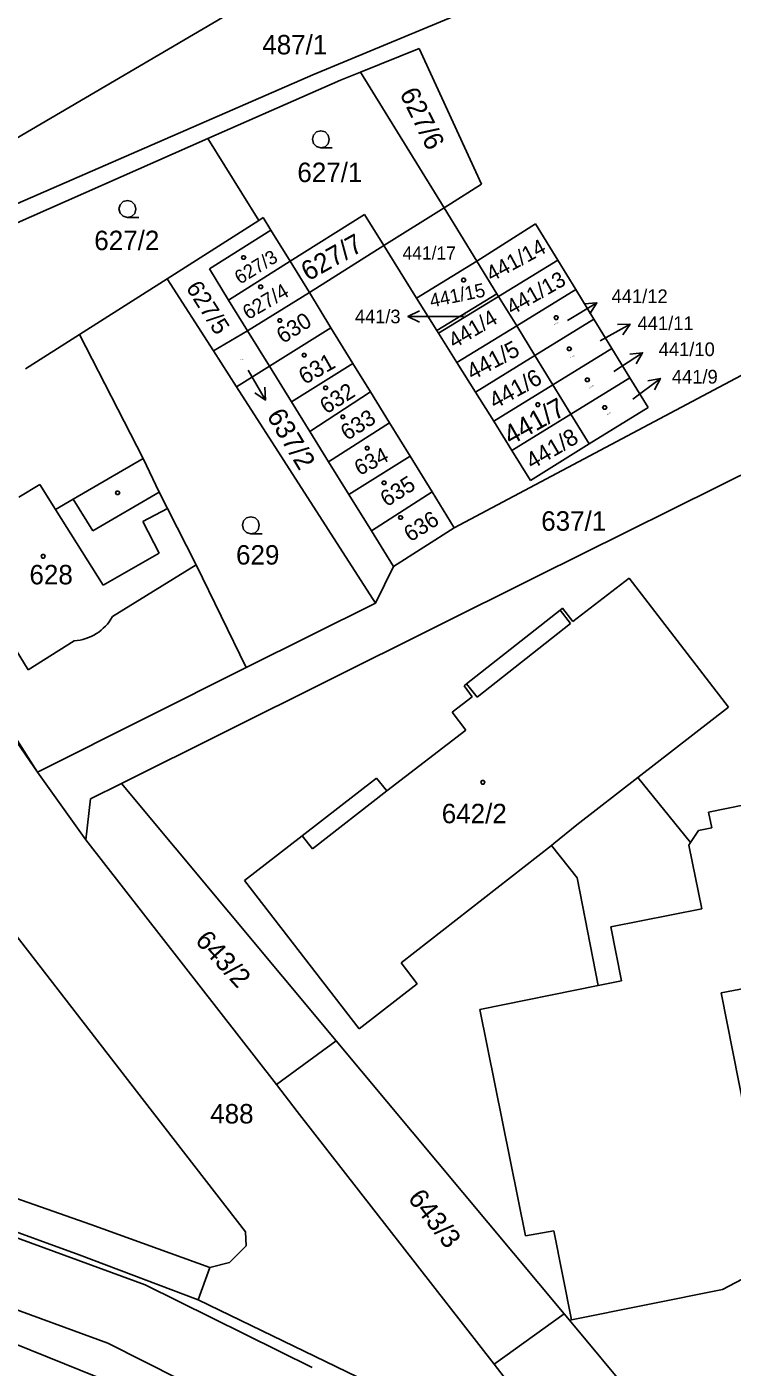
# Model space of a CAD drawing. Extents: x -621797 to -620972, y -1175539 to -1174697.
# Drawn here: x -621375.1 to -621313.4, y -1174986.3 to -1174869.1 of the extents above; entities that cross this region are included whole.
import ezdxf

# ---------------------------------------------------------------- set-up
doc = ezdxf.new("R2010")
doc.units = 0
for name, color, linetype in [('INZ mimo EON - nadz', 7, 'Continuous'), ('Rozvod plynu EON', 7, 'Continuous'), ('SDEL EON', 7, 'Continuous'), ('SDEL EON - popis', 7, 'Continuous'), ('Silnoproud EON', 7, 'Continuous'), ('Silnoproud EON - popis', 7, 'Continuous')]:
    doc.layers.add(name, color=color, linetype=linetype)

msp = doc.modelspace()

# ---------------------------------------------------------------- linework, layer by layer
at = {"layer": 'INZ mimo EON - nadz'}
for p, q in [((-621325.258, -1174893.266), (-621327.83, -1174894.81)), ((-621341.78, -1174894.436), (-621338.78, -1174894.45)), ((-621336.91, -1174894.46), (-621338.78, -1174894.45)), ((-621322.347, -1174895.114), (-621324.97, -1174896.57)), ((-621321.253, -1174897.617), (-621323.77, -1174899.25)), ((-621354.24, -1174901.748), (-621355.74, -1174899.15)), ((-621319.704, -1174899.855), (-621322.1, -1174901.66))]:
    msp.add_line(p, q, dxfattribs=at)
for points in [[(-621326.373, -1174893.352), (-621325.258, -1174893.266), (-621325.858, -1174894.209)], [(-621340.782, -1174894.94), (-621341.78, -1174894.436), (-621340.778, -1174893.94)], [(-621323.464, -1174895.162), (-621322.347, -1174895.114), (-621322.979, -1174896.037)], [(-621322.364, -1174897.742), (-621321.253, -1174897.617), (-621321.82, -1174898.581)], [(-621354.307, -1174900.632), (-621354.24, -1174901.748), (-621355.173, -1174901.132)], [(-621320.803, -1174900.057), (-621319.704, -1174899.855), (-621320.202, -1174900.856)]]:
    msp.add_lwpolyline(points, dxfattribs=at)
at = {"layer": 'Rozvod plynu EON'}
for points in [[(-621356.06, -1174889.15), (-621355.97, -1174889.3), (-621356.06, -1174889.45), (-621356.24, -1174889.45), (-621356.33, -1174889.3), (-621356.24, -1174889.15)], [(-621336.82, -1174891.11), (-621336.73, -1174891.26), (-621336.82, -1174891.41), (-621337, -1174891.41), (-621337.09, -1174891.26), (-621337, -1174891.11)], [(-621354.57, -1174891.7), (-621354.48, -1174891.85), (-621354.57, -1174892), (-621354.75, -1174892), (-621354.84, -1174891.85), (-621354.75, -1174891.7)], [(-621352.89, -1174894.65), (-621352.8, -1174894.8), (-621352.89, -1174894.95), (-621353.07, -1174894.95), (-621353.16, -1174894.8), (-621353.07, -1174894.65)], [(-621328.72, -1174894.4), (-621328.63, -1174894.55), (-621328.72, -1174894.7), (-621328.9, -1174894.7), (-621328.99, -1174894.55), (-621328.9, -1174894.4)], [(-621327.58, -1174897.12), (-621327.49, -1174897.27), (-621327.58, -1174897.42), (-621327.76, -1174897.42), (-621327.85, -1174897.27), (-621327.76, -1174897.12)], [(-621350.76, -1174897.67), (-621350.67, -1174897.82), (-621350.76, -1174897.97), (-621350.94, -1174897.97), (-621351.03, -1174897.82), (-621350.94, -1174897.67)], [(-621348.89, -1174900.54), (-621348.8, -1174900.69), (-621348.89, -1174900.84), (-621349.07, -1174900.84), (-621349.16, -1174900.69), (-621349.07, -1174900.54)], [(-621326, -1174899.84), (-621325.91, -1174899.99), (-621326, -1174900.14), (-621326.18, -1174900.14), (-621326.27, -1174899.99), (-621326.18, -1174899.84)], [(-621347.39, -1174903.07), (-621347.3, -1174903.22), (-621347.39, -1174903.37), (-621347.57, -1174903.37), (-621347.66, -1174903.22), (-621347.57, -1174903.07)], [(-621330.33, -1174902), (-621330.24, -1174902.15), (-621330.33, -1174902.3), (-621330.51, -1174902.3), (-621330.6, -1174902.15), (-621330.51, -1174902)], [(-621324.48, -1174902.25), (-621324.39, -1174902.4), (-621324.48, -1174902.55), (-621324.66, -1174902.55), (-621324.75, -1174902.4), (-621324.66, -1174902.25)], [(-621345.25, -1174905.81), (-621345.16, -1174905.96), (-621345.25, -1174906.11), (-621345.43, -1174906.11), (-621345.52, -1174905.96), (-621345.43, -1174905.81)], [(-621343.78, -1174908.83), (-621343.69, -1174908.98), (-621343.78, -1174909.13), (-621343.96, -1174909.13), (-621344.05, -1174908.98), (-621343.96, -1174908.83)], [(-621367.08, -1174909.7), (-621366.99, -1174909.85), (-621367.08, -1174910), (-621367.26, -1174910), (-621367.35, -1174909.85), (-621367.26, -1174909.7)], [(-621342.33, -1174911.86), (-621342.24, -1174912.01), (-621342.33, -1174912.16), (-621342.51, -1174912.16), (-621342.6, -1174912.01), (-621342.51, -1174911.86)], [(-621373.6, -1174915.26), (-621373.51, -1174915.41), (-621373.6, -1174915.56), (-621373.78, -1174915.56), (-621373.87, -1174915.41), (-621373.78, -1174915.26)], [(-621335.14, -1174935.01), (-621335.05, -1174935.16), (-621335.14, -1174935.31), (-621335.32, -1174935.31), (-621335.41, -1174935.16), (-621335.32, -1174935.01)]]:
    msp.add_lwpolyline(points, close=True, dxfattribs=at)
at = {"layer": 'SDEL EON'}
for points in [[(-621349.39, -1174879.7), (-621349.77, -1174879.6), (-621350.04, -1174879.33), (-621350.14, -1174878.96), (-621350.04, -1174878.59), (-621349.77, -1174878.32), (-621349.4, -1174878.22), (-621349.03, -1174878.32), (-621348.76, -1174878.59), (-621348.66, -1174878.97), (-621348.76, -1174879.35), (-621349.03, -1174879.62), (-621349.41, -1174879.72), (-621348.41, -1174879.72)], [(-621366.31, -1174885.79), (-621366.69, -1174885.69), (-621366.96, -1174885.42), (-621367.06, -1174885.05), (-621366.96, -1174884.68), (-621366.69, -1174884.41), (-621366.32, -1174884.31), (-621365.95, -1174884.41), (-621365.68, -1174884.68), (-621365.58, -1174885.06), (-621365.68, -1174885.44), (-621365.95, -1174885.71), (-621366.33, -1174885.81), (-621365.33, -1174885.81)], [(-621355.51, -1174913.43), (-621355.89, -1174913.33), (-621356.16, -1174913.06), (-621356.26, -1174912.69), (-621356.16, -1174912.32), (-621355.89, -1174912.05), (-621355.52, -1174911.95), (-621355.15, -1174912.05), (-621354.88, -1174912.32), (-621354.78, -1174912.7), (-621354.88, -1174913.08), (-621355.15, -1174913.35), (-621355.53, -1174913.45), (-621354.53, -1174913.45)]]:
    msp.add_lwpolyline(points, dxfattribs=at)
at = {"layer": 'SDEL EON - popis'}
for p, q in [((-621402.58, -1174893.11), (-621374.18, -1174934.27)), ((-621370.51, -1174896.02), (-621364.94, -1174906.86)), ((-621363.55, -1174909.81), (-621369.34, -1174913.17)), ((-621369.34, -1174913.17), (-621371.07, -1174910.42)), ((-621364.96, -1174912.38), (-621362.82, -1174911.23)), ((-621372.59, -1174911.31), (-621368.44, -1174917.92)), ((-621363.53, -1174915.14), (-621364.96, -1174912.38)), ((-621368.44, -1174917.92), (-621363.53, -1174915.14)), ((-621360.31, -1174916.14), (-621355.93, -1174925.14)), ((-621343.05, -1174916.31), (-621344.61, -1174919.49)), ((-621328.48, -1174920.12), (-621327.56, -1174921.28)), ((-621327.56, -1174921.28), (-621335.73, -1174927.72)), ((-621335.73, -1174927.72), (-621336.65, -1174926.56)), ((-621321.67, -1174934.73), (-621327.02, -1174938.88)), ((-621350.13, -1174940.97), (-621343.62, -1174935.92)), ((-621327.02, -1174938.88), (-621329.01, -1174940.51)), ((-621351.02, -1174939.83), (-621350.13, -1174940.97)), ((-621329.01, -1174940.51), (-621329.22, -1174940.68)), ((-621317.07, -1174940.41), (-621317.21, -1174940.64)), ((-621317.21, -1174940.64), (-621316.09, -1174946.21)), ((-621316.09, -1174946.21), (-621324.04, -1174947.8)), ((-621324.04, -1174947.8), (-621323.09, -1174952.5)), ((-621323.09, -1174952.5), (-621325.14, -1174952.92)), ((-621364.76, -1174979.08), (-621420.71, -1174958.62)), ((-621422.85, -1174964.14), (-621368.03, -1174984.17)), ((-621350.15, -1174986.32), (-621364.76, -1174979.08)), ((-621368.03, -1174984.17), (-621352.56, -1174991.96))]:
    msp.add_line(p, q, dxfattribs=at)
at = {"layer": 'Silnoproud EON'}
for p, q in [((-621350.07, -1174863.62), (-621380.4, -1174881.45)), ((-621334.3, -1174866.75), (-621350.1, -1174873.33)), ((-621340.79, -1174871.03), (-621345.92, -1174873.08)), ((-621335.36, -1174882.88), (-621340.79, -1174871.03)), ((-621350.1, -1174873.33), (-621377.07, -1174885.08)), ((-621347.68, -1174873.79), (-621359.28, -1174878.9)), ((-621345.92, -1174873.08), (-621347.68, -1174873.79)), ((-621338.62, -1174884.94), (-621345.92, -1174873.08)), ((-621359.28, -1174878.9), (-621380.1, -1174888.08)), ((-621359.28, -1174878.9), (-621354.81, -1174886.05)), ((-621338.62, -1174884.94), (-621335.36, -1174882.88)), ((-621343.89, -1174888.25), (-621338.62, -1174884.94)), ((-621338.62, -1174884.94), (-621335.75, -1174889.61)), ((-621284.44, -1174884.62), (-621337.73, -1174912.93)), ((-621354.81, -1174886.05), (-621362.84, -1174891.15)), ((-621354.81, -1174886.05), (-621354.43, -1174885.81)), ((-621354.43, -1174885.81), (-621353.77, -1174886.89)), ((-621345.59, -1174885.53), (-621352.09, -1174889.62)), ((-621345.59, -1174885.53), (-621343.89, -1174888.25)), ((-621335.75, -1174889.61), (-621330.63, -1174886.34)), ((-621330.63, -1174886.34), (-621328.68, -1174889.52)), ((-621359.15, -1174890.29), (-621353.77, -1174886.89)), ((-621353.77, -1174886.89), (-621352.09, -1174889.62)), ((-621350.4, -1174892.36), (-621343.89, -1174888.25)), ((-621343.89, -1174888.25), (-621341.02, -1174892.84)), ((-621357.47, -1174893.01), (-621352.09, -1174889.62)), ((-621352.09, -1174889.62), (-621350.4, -1174892.36)), ((-621341.02, -1174892.84), (-621335.75, -1174889.61)), ((-621334, -1174892.46), (-621335.75, -1174889.61)), ((-621328.68, -1174889.52), (-621333.85, -1174892.69)), ((-621328.68, -1174889.52), (-621327.1, -1174892.09)), ((-621362.84, -1174891.15), (-621370.51, -1174896.02)), ((-621358.79, -1174897.45), (-621362.84, -1174891.15)), ((-621357.47, -1174893.01), (-621359.15, -1174890.29)), ((-621350.4, -1174892.36), (-621355.81, -1174895.69)), ((-621348.51, -1174895.43), (-621350.4, -1174892.36)), ((-621339.24, -1174895.68), (-621334, -1174892.46)), ((-621333.85, -1174892.69), (-621334, -1174892.46)), ((-621327.1, -1174892.09), (-621332.27, -1174895.27)), ((-621327.1, -1174892.09), (-621325.53, -1174894.67)), ((-621355.81, -1174895.69), (-621357.47, -1174893.01)), ((-621339.24, -1174895.68), (-621341.02, -1174892.84)), ((-621333.85, -1174892.69), (-621339.1, -1174895.91)), ((-621332.27, -1174895.27), (-621333.85, -1174892.69)), ((-621325.53, -1174894.67), (-621330.68, -1174897.85)), ((-621325.53, -1174894.67), (-621323.95, -1174897.24)), ((-621370.51, -1174896.02), (-621375.24, -1174899.03)), ((-621355.81, -1174895.69), (-621358.79, -1174897.45)), ((-621353.88, -1174898.8), (-621355.81, -1174895.69)), ((-621348.51, -1174895.43), (-621353.88, -1174898.8)), ((-621346.59, -1174898.55), (-621348.51, -1174895.43)), ((-621339.1, -1174895.91), (-621339.24, -1174895.68)), ((-621337.5, -1174898.48), (-621339.1, -1174895.91)), ((-621332.27, -1174895.27), (-621337.5, -1174898.48)), ((-621330.68, -1174897.85), (-621332.27, -1174895.27)), ((-621358.79, -1174897.45), (-621356.76, -1174900.6)), ((-621330.68, -1174897.85), (-621335.88, -1174901.05)), ((-621329.1, -1174900.42), (-621330.68, -1174897.85)), ((-621323.95, -1174897.24), (-621329.1, -1174900.42)), ((-621323.95, -1174897.24), (-621322.38, -1174899.8)), ((-621356.76, -1174900.6), (-621353.88, -1174898.8)), ((-621351.96, -1174901.91), (-621353.88, -1174898.8)), ((-621346.59, -1174898.55), (-621351.96, -1174901.91)), ((-621345.05, -1174901.04), (-621346.59, -1174898.55)), ((-621335.88, -1174901.05), (-621337.5, -1174898.48)), ((-621356.76, -1174900.6), (-621344.61, -1174919.49)), ((-621329.1, -1174900.42), (-621334.28, -1174903.61)), ((-621327.52, -1174902.98), (-621329.1, -1174900.42)), ((-621322.38, -1174899.8), (-621327.52, -1174902.98)), ((-621322.38, -1174899.8), (-621320.78, -1174902.41)), ((-621350.36, -1174904.49), (-621351.96, -1174901.91)), ((-621345.05, -1174901.04), (-621350.36, -1174904.49)), ((-621343.39, -1174903.74), (-621345.05, -1174901.04)), ((-621334.28, -1174903.61), (-621335.88, -1174901.05)), ((-621327.52, -1174902.98), (-621332.69, -1174906.17)), ((-621325.93, -1174905.57), (-621327.52, -1174902.98)), ((-621320.78, -1174902.41), (-621325.93, -1174905.57)), ((-621343.39, -1174903.74), (-621348.72, -1174907.15)), ((-621341.59, -1174906.66), (-621343.39, -1174903.74)), ((-621332.69, -1174906.17), (-621334.28, -1174903.61)), ((-621302.7, -1174903.37), (-621330.5, -1174917.18)), ((-621348.72, -1174907.15), (-621350.36, -1174904.49)), ((-621331.06, -1174908.77), (-621332.69, -1174906.17)), ((-621325.93, -1174905.57), (-621331.06, -1174908.77)), ((-621371.07, -1174910.42), (-621364.94, -1174906.86)), ((-621364.94, -1174906.86), (-621363.55, -1174909.81)), ((-621346.95, -1174910), (-621348.72, -1174907.15)), ((-621341.59, -1174906.66), (-621346.95, -1174910)), ((-621339.67, -1174909.78), (-621341.59, -1174906.66)), ((-621390.48, -1174908.73), (-621374.18, -1174934.27)), ((-621375.81, -1174910.25), (-621373.96, -1174909.13)), ((-621373.96, -1174909.13), (-621372.59, -1174911.31)), ((-621363.55, -1174909.81), (-621362.82, -1174911.23)), ((-621344.98, -1174913.18), (-621346.95, -1174910)), ((-621339.67, -1174909.78), (-621344.98, -1174913.18)), ((-621337.73, -1174912.93), (-621339.67, -1174909.78)), ((-621372.59, -1174911.31), (-621371.07, -1174910.42)), ((-621362.82, -1174911.23), (-621360.31, -1174916.14)), ((-621343.05, -1174916.31), (-621344.98, -1174913.18)), ((-621337.73, -1174912.93), (-621343.05, -1174916.31)), ((-621360.31, -1174916.14), (-621367.63, -1174920.68)), ((-621330.5, -1174917.18), (-621366.83, -1174935.26)), ((-621327.36, -1174921.12), (-621322.43, -1174917.32)), ((-621322.43, -1174917.32), (-621313.74, -1174928.58)), ((-621344.61, -1174919.49), (-621355.93, -1174925.14)), ((-621336.65, -1174926.56), (-621328.48, -1174920.12)), ((-621328.48, -1174920.12), (-621328.26, -1174919.95)), ((-621328.26, -1174919.95), (-621327.36, -1174921.12)), ((-621374.99, -1174925.32), (-621377.69, -1174921)), ((-621370.98, -1174922.79), (-621374.99, -1174925.32)), ((-621355.93, -1174925.14), (-621373.78, -1174934.06)), ((-621337.92, -1174929.04), (-621336.16, -1174927.68)), ((-621336.85, -1174926.72), (-621336.65, -1174926.56)), ((-621336.16, -1174927.68), (-621336.85, -1174926.72)), ((-621313.74, -1174928.58), (-621321.67, -1174934.73)), ((-621336.72, -1174930.6), (-621337.92, -1174929.04)), ((-621343.62, -1174935.92), (-621336.72, -1174930.6)), ((-621315.48, -1174937.76), (-621293.93, -1174933.43)), ((-621373.78, -1174934.06), (-621374.18, -1174934.27)), ((-621369.95, -1174940.2), (-621374.18, -1174934.27)), ((-621366.83, -1174935.26), (-621369.53, -1174936.61)), ((-621348.05, -1174957.75), (-621366.83, -1174935.26)), ((-621351.02, -1174939.83), (-621344.54, -1174934.8)), ((-621344.54, -1174934.8), (-621343.62, -1174935.92)), ((-621321.67, -1174934.73), (-621317.07, -1174940.41)), ((-621369.53, -1174936.61), (-621369.95, -1174940.2)), ((-621364.82, -1174963.05), (-621384.13, -1174938.12)), ((-621315.2, -1174939.15), (-621315.48, -1174937.76)), ((-621317.07, -1174940.41), (-621316.36, -1174939.36)), ((-621316.36, -1174939.36), (-621315.2, -1174939.15)), ((-621353.29, -1174961.58), (-621369.95, -1174940.2)), ((-621356.07, -1174943.74), (-621351.02, -1174939.83)), ((-621329.22, -1174940.68), (-621342.37, -1174950.95)), ((-621326.99, -1174943.52), (-621329.22, -1174940.68)), ((-621346.05, -1174956.71), (-621356.07, -1174943.74)), ((-621325.14, -1174952.92), (-621326.99, -1174943.52)), ((-621342.37, -1174950.95), (-621340.96, -1174952.77)), ((-621340.96, -1174952.77), (-621346.05, -1174956.71)), ((-621335.5, -1174955.02), (-621325.14, -1174952.92)), ((-621312.24, -1174953.14), (-621314.39, -1174953.56)), ((-621314.39, -1174953.56), (-621311.32, -1174969.03)), ((-621428.04, -1174955.5), (-621370.54, -1174976.47)), ((-621331.5, -1174974.8), (-621335.5, -1174955.02)), ((-621353.29, -1174961.58), (-621348.05, -1174957.75)), ((-621328.13, -1174981.61), (-621348.05, -1174957.75)), ((-621351.48, -1174963.93), (-621353.29, -1174961.58)), ((-621356, -1174974.44), (-621364.82, -1174963.05)), ((-621334.24, -1174986.03), (-621351.48, -1174963.93)), ((-621390, -1174966.65), (-621369.52, -1174973.82)), ((-621369.52, -1174973.82), (-621359.12, -1174977.56)), ((-621355.92, -1174975.67), (-621356, -1174974.44)), ((-621329.02, -1174974.37), (-621331.5, -1174974.8)), ((-621327.47, -1174982.13), (-621329.02, -1174974.37)), ((-621357.38, -1174977.14), (-621355.92, -1174975.67)), ((-621370.54, -1174976.47), (-621360.13, -1174980.38)), ((-621360.13, -1174980.38), (-621359.12, -1174977.56)), ((-621359.12, -1174977.56), (-621357.38, -1174977.14)), ((-621309.68, -1174977.09), (-621314.28, -1174979.48)), ((-621364.26, -1174989.02), (-621388.75, -1174979.17)), ((-621332.26, -1174993.86), (-621360.13, -1174980.38)), ((-621314.28, -1174979.48), (-621327.47, -1174982.13)), ((-621334.24, -1174986.03), (-621328.13, -1174981.61)), ((-621327.66, -1174982.17), (-621328.13, -1174981.61)), ((-621327.47, -1174982.13), (-621327.66, -1174982.17)), ((-621305.54, -1175008.66), (-621327.66, -1174982.17)), ((-621329.73, -1174991.82), (-621334.24, -1174986.03))]:
    msp.add_line(p, q, dxfattribs=at)
msp.add_arc((-621371.206, -1174918.717), 4.079, 273.17523, 331.23439, dxfattribs=at)

# ---------------------------------------------------------------- texts
at = {"layer": 'INZ mimo EON - nadz'}
for s, height, p in [('441/12', 1.2, (-621323.972, -1174893.28)), ('441/3', 1.19, (-621346.411, -1174895.04)), ('441/11', 1.2, (-621321.702, -1174895.64)), ('441/10', 1.2, (-621319.852, -1174897.91)), ('441/9', 1.2, (-621318.702, -1174900.31)), ('488', 1.7, (-621359.073, -1174964.98))]:
    msp.add_text(s, height=height, dxfattribs=at).set_placement(p)
msp.add_text('637/2', height=1.7, rotation=300.97473, dxfattribs=at).set_placement((-621354.176, -1174903.126))
at = {"layer": 'Silnoproud EON - popis'}
for s, height, p in [('487/1', 1.7, (-621354.523, -1174871.54)), ('627/1', 1.7, (-621351.453, -1174882.7)), ('627/2', 1.7, (-621369.213, -1174888.65)), ('441/17', 1.14, (-621342.251, -1174889.47)), ('637/2', 0.1, (-621356.459, -1174898.25)), ('637/1', 1.7, (-621330.123, -1174913.17)), ('629', 1.7, (-621356.813, -1174916.13)), ('628', 1.7, (-621374.883, -1174917.86)), ('642/2', 1.7, (-621338.823, -1174938.74))]:
    msp.add_text(s, height=height, dxfattribs=at).set_placement(p)
for s, height, rotation, p in [('627/6', 1.7, 296.27648, (-621342.547, -1174874.948)), ('627/7', 1.7, 29.27814, (-621350.513, -1174891.397)), ('441/14', 1.36, 28.36141, (-621334.472, -1174891.442)), ('627/3', 1.2, 31.51268, (-621356.475, -1174891.678)), ('441/13', 1.36, 29.62192, (-621332.683, -1174894.359)), ('627/5', 1.5, 302.40713, (-621361.241, -1174891.936)), ('627/4', 1.28, 30.53865, (-621355.758, -1174894.776)), ('441/15', 1.2, 11.68834, (-621339.746, -1174893.676)), ('630', 1.4, 32.37212, (-621352.712, -1174896.863)), ('441/4', 1.36, 30.76783, (-621337.731, -1174897.283)), ('441/3', 0.1, 30.93972, (-621336.99, -1174894.486)), ('441/12', 0.1, 28.81978, (-621328.988, -1174895.203)), ('441/5', 1.45, 28.18952, (-621336.155, -1174900.052)), ('631', 1.45, 29.39274, (-621350.818, -1174900.439)), ('441/11', 0.1, 27.90304, (-621327.558, -1174898.113)), ('441/6', 1.45, 28.87707, (-621334.174, -1174902.571)), ('632', 1.4, 32.37212, (-621348.912, -1174903.023)), ('441/10', 0.1, 30.59595, (-621325.888, -1174900.753)), ('441/7', 1.7, 29.33544, (-621332.804, -1174905.742)), ('633', 1.4, 32.37212, (-621347.102, -1174905.333)), ('441/9', 0.1, 31.51268, (-621324.318, -1174903.063)), ('441/8', 1.45, 30.42406, (-621330.924, -1174907.851)), ('634', 1.35, 27.1582, (-621346.022, -1174908.39)), ('635', 1.4, 32.37212, (-621343.632, -1174911.133)), ('636', 1.4, 32.37212, (-621341.572, -1174914.203)), ('643/2', 1.7, 312.31929, (-621360.47, -1174949.054)), ('643/3', 1.7, 307.79293, (-621341.851, -1174971.542))]:
    msp.add_text(s, height=height, rotation=rotation, dxfattribs=at).set_placement(p)

doc.saveas('drawing.dxf')
